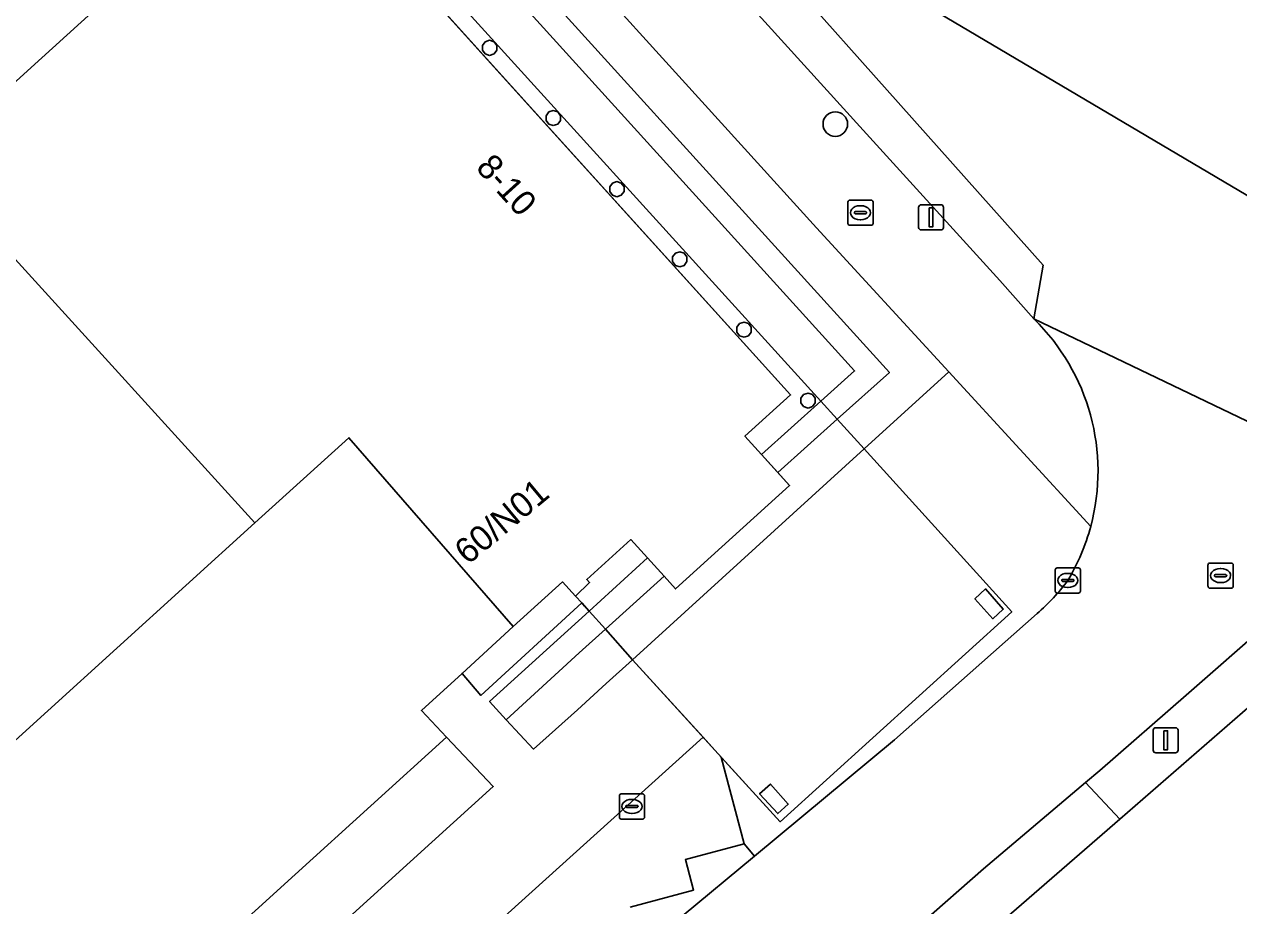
# Model space of a CAD drawing. Extents: x 161347 to 161881, y 382161 to 382804.
# Drawn here: x 161665.47 to 161713.79, y 382552.31 to 382587.37 of the extents above; entities that cross this region are included whole.
import ezdxf

# ---------------------------------------------------------------- set-up
doc = ezdxf.new("R2010")
doc.units = 0
for name, color, linetype in [('IMGEO_Boom', 7, 'Continuous'), ('IMGEO_Brandkraan', 7, 'Continuous'), ('IMGEO_Erf', 7, 'Continuous'), ('IMGEO_Fietspad_gesloten', 7, 'Continuous'), ('IMGEO_Groenvoorziening', 7, 'Continuous'), ('IMGEO_Haag', 7, 'Continuous'), ('IMGEO_Kolk', 7, 'Continuous'), ('IMGEO_Lichtmast', 7, 'Continuous'), ('IMGEO_Pand', 7, 'Continuous'), ('IMGEO_Pand_nummerreeks', 7, 'Continuous'), ('IMGEO_Pand_overbouw', 7, 'Continuous'), ('IMGEO_Parkeervlak_gesloten', 7, 'Continuous'), ('IMGEO_Parkeervlak_open', 7, 'Continuous'), ('IMGEO_Rijbaan_lokaal_gesloten', 7, 'Continuous'), ('IMGEO_Rijbaan_lokaal_open', 7, 'Continuous'), ('IMGEO_Rioolput', 7, 'Continuous'), ('IMGEO_Voetpad_gesloten', 7, 'Continuous'), ('IMGEO_Voetpad_open', 7, 'Continuous')]:
    doc.layers.add(name, color=color, linetype=linetype)

msp = doc.modelspace()

# ---------------------------------------------------------------- linework, layer by layer
at = {"layer": 'IMGEO_Boom'}
msp.add_circle((161697.739, 382583.399), 0.489, dxfattribs=at)
at = {"layer": 'IMGEO_Brandkraan'}
for p, q in [((161698.24, 382579.446), (161698.24, 382580.298)), ((161698.315, 382580.372), (161699.167, 382580.372)), ((161699.241, 382580.298), (161699.241, 382579.446)), ((161698.499, 382579.866), (161698.499, 382579.878)), ((161698.937, 382579.829), (161698.539, 382579.829)), ((161698.542, 382579.915), (161698.94, 382579.915)), ((161698.728, 382580.152), (161698.753, 382580.152)), ((161698.983, 382579.878), (161698.983, 382579.866)), ((161699.167, 382579.372), (161698.315, 382579.372)), ((161698.751, 382579.592), (161698.726, 382579.592))]:
    msp.add_line(p, q, dxfattribs=at)
for points in [[(161698.24, 382579.446), (161698.24, 382580.298)], [(161698.315, 382580.372), (161699.167, 382580.372)], [(161699.241, 382580.298), (161699.241, 382579.446)], [(161699.167, 382579.372), (161698.315, 382579.372)]]:
    msp.add_lwpolyline(points, dxfattribs=at)
for centre, radius, start, end in [((161698.317, 382580.296), 0.0765, 91.552, 178.448), ((161698.317, 382580.296), 0.0765, 91.552, 178.448), ((161699.165, 382580.296), 0.0765, 1.552, 88.448), ((161699.165, 382580.296), 0.0765, 1.552, 88.448), ((161698.539, 382579.875), 0.0403, 85.8775, 175.7526), ((161698.536, 382579.865), 0.0366, 178.938, 274.7102), ((161698.94, 382579.872), 0.043, 264.8664, 352.4533), ((161698.944, 382579.877), 0.0386, 1.7309, 96.639), ((161698.317, 382579.448), 0.0765, 181.552, 268.448), ((161698.317, 382579.448), 0.0765, 181.552, 268.448), ((161699.165, 382579.448), 0.0765, 271.552, 358.448), ((161699.165, 382579.448), 0.0765, 271.552, 358.448)]:
    msp.add_arc(centre, radius, start, end, dxfattribs=at)
for centre, major_axis, ratio, start_param, end_param in [((161698.727, 382579.872), (-0.387, 0.002), 0.722429, 4.712389, 7.853982), ((161698.752, 382579.872), (-0.39, 0.002), 0.717154, 1.570796, 4.712389)]:
    msp.add_ellipse(centre, major_axis=major_axis, ratio=ratio, start_param=start_param, end_param=end_param, dxfattribs=at)
at = {"layer": 'IMGEO_Erf'}
for points in [[(161572.092, 382591.77), (161539.981, 382570.178), (161537.341, 382557.85), (161565.95, 382511.235), (161572.292, 382501.343), (161572.851, 382501.493), (161573.727, 382500), (161581.489, 382486.772), (161593.113, 382483.942), (161618.484, 382500), (161639.588, 382513.357), (161643.126, 382515.61), (161643.533, 382515.936), (161628.206, 382532.98), (161623.055, 382540.753), (161664.71, 382578.468), (161661.6, 382581.894), (161665.593, 382585.519), (161669.295, 382588.879)], [(161794.971, 382530.118), (161792.241, 382536.131), (161792.378, 382536.972), (161792.323, 382537.821), (161791.654, 382539.638), (161791.061, 382540.405), (161790.328, 382541.011), (161790.189, 382541.423), (161789.107, 382540.979), (161788.094, 382543.265), (161787.424, 382542.968), (161782.001, 382556.605), (161781.188, 382558.978), (161780.231, 382559.421), (161779.298, 382559.715), (161776.187, 382560.249), (161770.93, 382560.454), (161716.681, 382562.374), (161709.058, 382555.75), (161702.444, 382550.002), (161681.121, 382531.471), (161671.366, 382522.817), (161670.351, 382521.638), (161669.529, 382520.317)]]:
    msp.add_lwpolyline(points, dxfattribs=at)
at = {"layer": 'IMGEO_Fietspad_gesloten'}
msp.add_lwpolyline([(161676.15, 382608.16), (161698.844, 382583.161), (161704.285, 382577.171), (161705.643, 382575.646), (161706.007, 382577.787), (161673.989, 382613.712)], dxfattribs=at)
at = {"layer": 'IMGEO_Groenvoorziening'}
for points in [[(161687.944, 382564.02), (161683.982, 382560.43), (161684.649, 382559.706), (161687.547, 382562.36), (161688.589, 382563.302)], [(161689.676, 382562.09), (161688.589, 382563.302), (161687.547, 382562.36), (161684.649, 382559.706), (161685.729, 382558.534), (161687.482, 382560.098), (161688.624, 382561.141)], [(161676.253, 382553.55), (161643.672, 382523.978), (161645.836, 382522.287), (161652.099, 382527.995), (161684.128, 382557.046), (161682.265, 382559.016)]]:
    msp.add_lwpolyline(points, close=True, dxfattribs=at)
msp.add_lwpolyline([(161691.651, 382551.884), (161694.524, 382554.274), (161694.116, 382554.765), (161691.774, 382554.142), (161692.098, 382552.924), (161690.119, 382552.398), (161689.571, 382552.252)], dxfattribs=at)
at = {"layer": 'IMGEO_Haag'}
msp.add_lwpolyline([(161676.253, 382553.55), (161643.672, 382523.978), (161645.836, 382522.287), (161652.099, 382527.995), (161684.128, 382557.046), (161682.265, 382559.016)], close=True, dxfattribs=at)
at = {"layer": 'IMGEO_Kolk'}
for p, q in [((161706.566, 382565.745), (161707.418, 382565.745)), ((161706.491, 382564.819), (161706.491, 382565.671)), ((161706.793, 382565.288), (161707.191, 382565.288)), ((161706.979, 382565.525), (161707.004, 382565.525)), ((161707.492, 382565.671), (161707.492, 382564.819)), ((161706.75, 382565.239), (161706.75, 382565.251)), ((161707.188, 382565.202), (161706.79, 382565.202)), ((161707.002, 382564.965), (161706.977, 382564.965)), ((161707.234, 382565.251), (161707.234, 382565.239)), ((161707.418, 382564.745), (161706.566, 382564.745)), ((161689.147, 382555.829), (161689.147, 382556.681)), ((161689.222, 382556.755), (161690.074, 382556.755)), ((161690.148, 382556.681), (161690.148, 382555.829)), ((161689.406, 382556.249), (161689.406, 382556.261)), ((161689.844, 382556.212), (161689.446, 382556.212)), ((161689.449, 382556.298), (161689.847, 382556.298)), ((161689.635, 382556.535), (161689.66, 382556.535)), ((161689.89, 382556.261), (161689.89, 382556.249)), ((161690.074, 382555.755), (161689.222, 382555.755)), ((161689.658, 382555.975), (161689.633, 382555.975))]:
    msp.add_line(p, q, dxfattribs=at)
for points in [[(161706.566, 382565.745), (161707.418, 382565.745)], [(161706.491, 382564.819), (161706.491, 382565.671)], [(161707.492, 382565.671), (161707.492, 382564.819)], [(161707.418, 382564.745), (161706.566, 382564.745)], [(161689.147, 382555.829), (161689.147, 382556.681)], [(161689.222, 382556.755), (161690.074, 382556.755)], [(161690.148, 382556.681), (161690.148, 382555.829)], [(161690.074, 382555.755), (161689.222, 382555.755)]]:
    msp.add_lwpolyline(points, dxfattribs=at)
for centre, radius, start, end in [((161706.568, 382565.669), 0.0765, 91.552, 178.448), ((161706.568, 382565.669), 0.0765, 91.552, 178.448), ((161707.416, 382565.669), 0.0765, 1.552, 88.448), ((161707.416, 382565.669), 0.0765, 1.552, 88.448), ((161706.79, 382565.248), 0.0403, 85.8775, 175.7526), ((161707.195, 382565.25), 0.0386, 1.7309, 96.639), ((161706.568, 382564.821), 0.0765, 181.552, 268.448), ((161706.568, 382564.821), 0.0765, 181.552, 268.448), ((161706.787, 382565.238), 0.0366, 178.938, 274.7102), ((161707.191, 382565.245), 0.043, 264.8664, 352.4533), ((161707.416, 382564.821), 0.0765, 271.552, 358.448), ((161707.416, 382564.821), 0.0765, 271.552, 358.448), ((161689.224, 382556.679), 0.0765, 91.552, 178.448), ((161689.224, 382556.679), 0.0765, 91.552, 178.448), ((161690.072, 382556.679), 0.0765, 1.552, 88.448), ((161690.072, 382556.679), 0.0765, 1.552, 88.448), ((161689.446, 382556.258), 0.0403, 85.8775, 175.7526), ((161689.443, 382556.248), 0.0366, 178.938, 274.7102), ((161689.847, 382556.255), 0.043, 264.8664, 352.4533), ((161689.851, 382556.26), 0.0386, 1.7309, 96.639), ((161689.224, 382555.831), 0.0765, 181.552, 268.448), ((161689.224, 382555.831), 0.0765, 181.552, 268.448), ((161690.072, 382555.831), 0.0765, 271.552, 358.448), ((161690.072, 382555.831), 0.0765, 271.552, 358.448)]:
    msp.add_arc(centre, radius, start, end, dxfattribs=at)
for centre, major_axis, ratio, start_param, end_param in [((161706.978, 382565.245), (-0.387, 0.002), 0.722429, 4.712389, 7.853982), ((161707.003, 382565.245), (-0.39, 0.002), 0.717154, 1.570796, 4.712389), ((161689.634, 382556.255), (-0.387, 0.002), 0.722429, 4.712389, 7.853982), ((161689.659, 382556.255), (-0.39, 0.002), 0.717154, 1.570796, 4.712389)]:
    msp.add_ellipse(centre, major_axis=major_axis, ratio=ratio, start_param=start_param, end_param=end_param, dxfattribs=at)
at = {"layer": 'IMGEO_Lichtmast'}
for p, q in [((161701.054, 382579.288), (161701.054, 382580.088)), ((161701.054, 382580.088), (161701.054, 382579.288)), ((161701.154, 382580.188), (161701.944, 382580.188)), ((161701.944, 382580.188), (161701.154, 382580.188)), ((161702.044, 382580.088), (161702.044, 382579.288)), ((161702.044, 382579.288), (161702.044, 382580.088)), ((161701.944, 382579.188), (161701.154, 382579.188)), ((161701.154, 382579.188), (161701.944, 382579.188)), ((161710.388, 382558.488), (161710.388, 382559.288)), ((161710.388, 382559.288), (161710.388, 382558.488)), ((161710.488, 382559.388), (161711.278, 382559.388)), ((161711.278, 382559.388), (161710.488, 382559.388)), ((161711.378, 382559.288), (161711.378, 382558.488)), ((161711.378, 382558.488), (161711.378, 382559.288)), ((161711.278, 382558.388), (161710.488, 382558.388)), ((161710.488, 382558.388), (161711.278, 382558.388))]:
    msp.add_line(p, q, dxfattribs=at)
for points in [[(161701.474, 382580.063), (161701.624, 382580.063), (161701.624, 382579.313), (161701.474, 382579.313), (161701.474, 382580.063)], [(161710.808, 382559.263), (161710.958, 382559.263), (161710.958, 382558.513), (161710.808, 382558.513), (161710.808, 382559.263)]]:
    msp.add_lwpolyline(points, dxfattribs=at)
for centre, start, end in [((161701.154, 382580.088), 90, 180), ((161701.154, 382580.088), 90, 180), ((161701.944, 382580.088), 0, 90), ((161701.944, 382580.088), 360, 90), ((161701.154, 382579.288), 180, 270), ((161701.154, 382579.288), 180, 270), ((161701.944, 382579.288), 270, 0), ((161701.944, 382579.288), 270, 0), ((161710.488, 382559.288), 90, 180), ((161710.488, 382559.288), 90, 180), ((161711.278, 382559.288), 0, 90), ((161711.278, 382559.288), 360, 90), ((161710.488, 382558.488), 180, 270), ((161710.488, 382558.488), 180, 270), ((161711.278, 382558.488), 270, 0), ((161711.278, 382558.488), 270, 0)]:
    msp.add_arc(centre, 0.1, start, end, dxfattribs=at)
at = {"layer": 'IMGEO_Pand'}
for points in [[(161684.928, 382563.407), (161686.88, 382565.188), (161687.408, 382564.618), (161687.965, 382565.168), (161687.847, 382565.287), (161689.608, 382566.87), (161690.27, 382566.139), (161690.926, 382565.414), (161691.385, 382564.907), (161695.922, 382569.028), (161695.455, 382569.543), (161694.808, 382570.257), (161694.144, 382570.989), (161695.962, 382572.626), (161678.502, 382591.938), (161675.871, 382594.848), (161669.295, 382588.879), (161665.593, 382585.519), (161661.6, 382581.894), (161664.71, 382578.468), (161674.636, 382567.532), (161678.388, 382570.921)], [(161683.986, 382586.133), (161684.162, 382586.19), (161684.271, 382586.34), (161684.271, 382586.526), (161684.162, 382586.676), (161683.986, 382586.733), (161683.81, 382586.676), (161683.701, 382586.526), (161683.701, 382586.34), (161683.81, 382586.19)], [(161686.518, 382583.338), (161686.694, 382583.395), (161686.803, 382583.545), (161686.803, 382583.731), (161686.694, 382583.881), (161686.518, 382583.938), (161686.342, 382583.881), (161686.233, 382583.731), (161686.233, 382583.545), (161686.342, 382583.395)], [(161689.047, 382580.511), (161689.223, 382580.568), (161689.332, 382580.718), (161689.332, 382580.904), (161689.223, 382581.054), (161689.047, 382581.111), (161688.871, 382581.054), (161688.762, 382580.904), (161688.762, 382580.718), (161688.871, 382580.568)], [(161691.551, 382577.722), (161691.727, 382577.779), (161691.836, 382577.929), (161691.836, 382578.115), (161691.727, 382578.265), (161691.551, 382578.322), (161691.375, 382578.265), (161691.266, 382578.115), (161691.266, 382577.929), (161691.375, 382577.779)], [(161694.107, 382574.921), (161694.283, 382574.978), (161694.392, 382575.128), (161694.392, 382575.314), (161694.283, 382575.464), (161694.107, 382575.521), (161693.931, 382575.464), (161693.822, 382575.314), (161693.822, 382575.128), (161693.931, 382574.978)], [(161696.653, 382572.101), (161696.829, 382572.158), (161696.938, 382572.308), (161696.938, 382572.494), (161696.829, 382572.644), (161696.653, 382572.701), (161696.477, 382572.644), (161696.368, 382572.494), (161696.368, 382572.308), (161696.477, 382572.158)], [(161684.928, 382563.407), (161678.388, 382570.921), (161674.636, 382567.532), (161638.938, 382535.131), (161638.008, 382536.155), (161634.759, 382533.207), (161640.057, 382527.369), (161643.393, 382523.725), (161643.672, 382523.978), (161676.253, 382553.55), (161682.265, 382559.016), (161681.273, 382560.072), (161682.89, 382561.547)], [(161704.011, 382563.721), (161704.425, 382564.101), (161703.722, 382564.905), (161703.294, 382564.513)], [(161695.452, 382555.969), (161695.866, 382556.346), (161695.158, 382557.143), (161694.726, 382556.762)]]:
    msp.add_lwpolyline(points, close=True, dxfattribs=at)
at = {"layer": 'IMGEO_Pand_overbouw'}
msp.add_lwpolyline([(161675.871, 382594.848), (161695.962, 382572.626), (161694.144, 382570.989), (161694.808, 382570.257), (161695.922, 382569.028), (161691.385, 382564.907), (161690.926, 382565.414), (161690.27, 382566.139), (161689.608, 382566.87), (161687.847, 382565.287), (161687.965, 382565.168), (161687.408, 382564.618), (161687.648, 382564.351), (161687.688, 382564.306), (161687.758, 382564.227), (161687.944, 382564.02), (161688.589, 382563.302), (161689.676, 382562.09), (161695.542, 382555.644), (161704.759, 382563.996), (161698.891, 382570.474), (161697.816, 382571.661), (161697.168, 382572.377), (161680.52, 382590.719)], dxfattribs=at)
at = {"layer": 'IMGEO_Parkeervlak_gesloten'}
msp.add_lwpolyline([(161648.064, 382519.038), (161648.744, 382519.518), (161643.393, 382523.725), (161640.057, 382527.369), (161634.759, 382533.207), (161638.008, 382536.155), (161638.938, 382535.131), (161674.636, 382567.532), (161664.71, 382578.468), (161623.055, 382540.753), (161628.206, 382532.98), (161643.533, 382515.936), (161643.62, 382516.005)], close=True, dxfattribs=at)
at = {"layer": 'IMGEO_Parkeervlak_open'}
msp.add_lwpolyline([(161689.571, 382552.252), (161690.119, 382552.398), (161692.098, 382552.924), (161691.774, 382554.142), (161694.116, 382554.765), (161693.197, 382558.221), (161692.48, 382559.009), (161680.506, 382548.198)], dxfattribs=at)
at = {"layer": 'IMGEO_Rijbaan_lokaal_gesloten'}
for points in [[(161780.196, 382571.153), (161779.525, 382578.285), (161728.827, 382571.874), (161701.238, 382588.176), (161661.586, 382630.771), (161622.627, 382671.947), (161592.087, 382705.487), (161563.602, 382736.77)], [(161575.378, 382721.548), (161577.619, 382719.049), (161589.767, 382705.692), (161601.665, 382692.722), (161616.607, 382676.142), (161624.391, 382667.348), (161636.242, 382654.182), (161636.579, 382653.807), (161653.899, 382634.564), (161673.989, 382613.712), (161706.007, 382577.787), (161705.643, 382575.646), (161721.925, 382567.837)], [(161707.699, 382557.212), (161708.262, 382557.69), (161711.696, 382560.686), (161715.002, 382563.572), (161715.917, 382564.341), (161716.541, 382564.759), (161721.724, 382567.727), (161721.925, 382567.837), (161705.643, 382575.646)], [(161705.768, 382563.927), (161700.093, 382558.908), (161694.524, 382554.274), (161691.651, 382551.884), (161690.206, 382550.598), (161681.712, 382543.025), (161666.712, 382529.643)], [(161670.026, 382524.435), (161670.597, 382524.931), (161669.286, 382526.443), (161672.516, 382529.253), (161677.271, 382533.418), (161681.896, 382537.521), (161686.794, 382541.797), (161691.965, 382546.197), (161696.498, 382550.18), (161697.808, 382548.669), (161698.795, 382549.536), (161701.128, 382551.574), (161703.639, 382553.768), (161707.699, 382557.212)]]:
    msp.add_lwpolyline(points, dxfattribs=at)
for centre, radius, start, end in [((161699.725, 382569.59), 8.468, 344.9712, 45.6612), ((161699.69, 382569.605), 8.505, 329.164, 344.9353), ((161700.456, 382570.093), 8.138, 310.7475, 323.4414)]:
    msp.add_arc(centre, radius, start, end, dxfattribs=at)
at = {"layer": 'IMGEO_Rijbaan_lokaal_open'}
for points in [[(161698.891, 382570.474), (161689.676, 382562.09), (161692.48, 382559.009), (161693.197, 382558.221), (161695.542, 382555.644), (161704.759, 382563.996)], [(161703.294, 382564.513), (161703.722, 382564.905), (161704.425, 382564.101), (161704.011, 382563.721)], [(161680.506, 382548.198), (161692.48, 382559.009), (161689.676, 382562.09), (161688.624, 382561.141), (161687.482, 382560.098), (161685.729, 382558.534), (161684.649, 382559.706), (161683.982, 382560.43), (161687.944, 382564.02), (161687.648, 382564.351), (161683.638, 382560.672), (161682.89, 382561.547), (161681.273, 382560.072), (161682.265, 382559.016), (161684.128, 382557.046), (161652.099, 382527.995), (161653.308, 382523.528), (161654.315, 382524.377), (161662.915, 382532.2), (161671.874, 382540.317)], [(161695.866, 382556.346), (161695.452, 382555.969), (161694.726, 382556.762), (161695.158, 382557.143)]]:
    msp.add_lwpolyline(points, close=True, dxfattribs=at)
at = {"layer": 'IMGEO_Rioolput'}
for p, q in [((161712.569, 382565.012), (161712.569, 382565.864)), ((161712.644, 382565.938), (161713.496, 382565.938)), ((161713.57, 382565.864), (161713.57, 382565.012)), ((161712.828, 382565.432), (161712.828, 382565.444)), ((161713.266, 382565.395), (161712.868, 382565.395)), ((161712.871, 382565.481), (161713.269, 382565.481)), ((161713.057, 382565.718), (161713.082, 382565.718)), ((161713.312, 382565.444), (161713.312, 382565.432)), ((161713.496, 382564.938), (161712.644, 382564.938)), ((161713.08, 382565.158), (161713.055, 382565.158))]:
    msp.add_line(p, q, dxfattribs=at)
for points in [[(161712.569, 382565.012), (161712.569, 382565.864)], [(161712.644, 382565.938), (161713.496, 382565.938)], [(161713.57, 382565.864), (161713.57, 382565.012)], [(161713.496, 382564.938), (161712.644, 382564.938)]]:
    msp.add_lwpolyline(points, dxfattribs=at)
for centre, radius, start, end in [((161712.646, 382565.862), 0.0765, 91.552, 178.448), ((161712.646, 382565.862), 0.0765, 91.552, 178.448), ((161713.494, 382565.862), 0.0765, 1.552, 88.448), ((161713.494, 382565.862), 0.0765, 1.552, 88.448), ((161712.868, 382565.441), 0.0403, 85.8775, 175.7526), ((161712.865, 382565.431), 0.0366, 178.938, 274.7102), ((161713.269, 382565.438), 0.043, 264.8664, 352.4533), ((161713.273, 382565.443), 0.0386, 1.7309, 96.639), ((161712.646, 382565.014), 0.0765, 181.552, 268.448), ((161712.646, 382565.014), 0.0765, 181.552, 268.448), ((161713.494, 382565.014), 0.0765, 271.552, 358.448), ((161713.494, 382565.014), 0.0765, 271.552, 358.448)]:
    msp.add_arc(centre, radius, start, end, dxfattribs=at)
for centre, major_axis, ratio, start_param, end_param in [((161713.056, 382565.438), (-0.387, 0.002), 0.722429, 4.712389, 7.853982), ((161713.081, 382565.438), (-0.39, 0.002), 0.717154, 1.570796, 4.712389)]:
    msp.add_ellipse(centre, major_axis=major_axis, ratio=ratio, start_param=start_param, end_param=end_param, dxfattribs=at)
at = {"layer": 'IMGEO_Voetpad_gesloten'}
for points in [[(161697.816, 382571.661), (161699.891, 382573.522), (161681.259, 382594.056), (161681.066, 382594.264), (161680.342, 382593.591), (161681.865, 382591.932), (161698.504, 382573.577), (161697.168, 382572.377)], [(161697.168, 382572.377), (161694.808, 382570.257), (161695.455, 382569.543), (161697.816, 382571.661)], [(161688.589, 382563.302), (161690.926, 382565.414), (161690.27, 382566.139), (161687.944, 382564.02)]]:
    msp.add_lwpolyline(points, close=True, dxfattribs=at)
at = {"layer": 'IMGEO_Voetpad_open'}
for points in [[(161661.71, 382623.972), (161656.463, 382629.372), (161650.877, 382635.381), (161646.136, 382639.799), (161645.871, 382640.073), (161642.272, 382638.554), (161653.29, 382627.1), (161679.75, 382598.28), (161682.518, 382595.225), (161696.997, 382579.273), (161702.259, 382573.539), (161707.903, 382567.394)], [(161705.643, 382575.646), (161704.285, 382577.171), (161698.844, 382583.161), (161676.15, 382608.16), (161661.71, 382623.972)], [(161702.259, 382573.539), (161698.891, 382570.474), (161704.759, 382563.996), (161695.542, 382555.644), (161693.197, 382558.221), (161694.116, 382554.765), (161694.524, 382554.274), (161700.093, 382558.908), (161705.768, 382563.927)], [(161707.903, 382567.394), (161702.259, 382573.539)]]:
    msp.add_lwpolyline(points, dxfattribs=at)
for points in [[(161680.52, 382590.719), (161681.865, 382591.932), (161680.342, 382593.591), (161681.066, 382594.264), (161681.259, 382594.056), (161699.891, 382573.522), (161697.816, 382571.661), (161698.891, 382570.474), (161702.259, 382573.539), (161696.997, 382579.273), (161682.518, 382595.225), (161679.75, 382598.28), (161676.366, 382595.297)], [(161675.871, 382594.848), (161678.502, 382591.938), (161695.962, 382572.626), (161694.144, 382570.989), (161694.808, 382570.257), (161697.168, 382572.377), (161680.52, 382590.719), (161676.366, 382595.297)], [(161697.168, 382572.377), (161698.504, 382573.577), (161681.865, 382591.932), (161680.52, 382590.719)], [(161683.986, 382586.133), (161683.81, 382586.19), (161683.701, 382586.34), (161683.701, 382586.526), (161683.81, 382586.676), (161683.986, 382586.733), (161684.162, 382586.676), (161684.271, 382586.526), (161684.271, 382586.34), (161684.162, 382586.19)], [(161686.518, 382583.338), (161686.342, 382583.395), (161686.233, 382583.545), (161686.233, 382583.731), (161686.342, 382583.881), (161686.518, 382583.938), (161686.694, 382583.881), (161686.803, 382583.731), (161686.803, 382583.545), (161686.694, 382583.395)], [(161689.047, 382580.511), (161688.871, 382580.568), (161688.762, 382580.718), (161688.762, 382580.904), (161688.871, 382581.054), (161689.047, 382581.111), (161689.223, 382581.054), (161689.332, 382580.904), (161689.332, 382580.718), (161689.223, 382580.568)], [(161691.551, 382577.722), (161691.375, 382577.779), (161691.266, 382577.929), (161691.266, 382578.115), (161691.375, 382578.265), (161691.551, 382578.322), (161691.727, 382578.265), (161691.836, 382578.115), (161691.836, 382577.929), (161691.727, 382577.779)], [(161694.107, 382574.921), (161693.931, 382574.978), (161693.822, 382575.128), (161693.822, 382575.314), (161693.931, 382575.464), (161694.107, 382575.521), (161694.283, 382575.464), (161694.392, 382575.314), (161694.392, 382575.128), (161694.283, 382574.978)], [(161696.653, 382572.101), (161696.477, 382572.158), (161696.368, 382572.308), (161696.368, 382572.494), (161696.477, 382572.644), (161696.653, 382572.701), (161696.829, 382572.644), (161696.938, 382572.494), (161696.938, 382572.308), (161696.829, 382572.158)], [(161689.676, 382562.09), (161698.891, 382570.474), (161697.816, 382571.661), (161695.455, 382569.543), (161695.922, 382569.028), (161691.385, 382564.907), (161690.926, 382565.414), (161688.589, 382563.302)], [(161687.944, 382564.02), (161690.27, 382566.139), (161689.608, 382566.87), (161687.847, 382565.287), (161687.965, 382565.168), (161687.408, 382564.618), (161687.648, 382564.351)], [(161687.408, 382564.618), (161686.88, 382565.188), (161684.928, 382563.407), (161682.89, 382561.547), (161683.638, 382560.672), (161687.648, 382564.351)], [(161716.681, 382562.374), (161715.002, 382563.572), (161711.696, 382560.686), (161708.262, 382557.69), (161707.699, 382557.212), (161709.058, 382555.75)], [(161709.058, 382555.75), (161707.699, 382557.212), (161703.639, 382553.768), (161701.128, 382551.574), (161702.444, 382550.002)]]:
    msp.add_lwpolyline(points, close=True, dxfattribs=at)
for centre, radius, start, end in [((161699.725, 382569.59), 8.468, 344.9712, 45.6612), ((161699.69, 382569.605), 8.505, 329.164, 344.9353), ((161700.456, 382570.093), 8.138, 310.7475, 323.4414)]:
    msp.add_arc(centre, radius, start, end, dxfattribs=at)

# ---------------------------------------------------------------- texts
at = {"layer": 'IMGEO_Pand_nummerreeks'}
for s, rotation, p in [('8-10', 312.1956, (161683.397, 382581.637)), ('60/N01', 39.7743, (161683.119, 382565.839))]:
    msp.add_text(s, height=1, rotation=rotation, dxfattribs=at).set_placement(p)

doc.saveas('drawing.dxf')
